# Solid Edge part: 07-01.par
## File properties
Author: edge
Template: jis part.par
Last saved by: edge
Revision: 25
Application: Solid Edge
Material: 鋼鉄
面のスタイル: Steel
塗りつぶしのスタイル: ANSI32(Steel)
バーチャルスタイル: 鋼鉄 機械仕上げ
Coef. of Thermal Exp: 0.0
Thermal Conductivity: 32.0
Specific Heat: 481.0
Modulus of Elasticity: 199947953000.0
Poisson's Ratio: 0.29
Yield Stress: 262000766.0
Ultimate Stress: 358527364.0
Elongation: 0.0
文書内容のタイプ: 0
Density: 7833.000 kg/m^3
Accuracy: 0.990
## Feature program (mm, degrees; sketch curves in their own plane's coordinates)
sketch for "ExtrudedProtrusion_1" plane through (0, 0, 0) normal (1, 0, 0) x-axis (0, 1, 0)
  circle centre (0, 0) radius 20
extrude "ExtrudedProtrusion_1" add finite 150 along +normal  FiniteDepth2 = 150 mm
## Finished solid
Body 1: solid body, 3 faces, 2 edges, 0 vertices.
  Faces by surface: plane 2, cylinder 1
  Edges by curve: circle 2
Bounding box of the edges (mm): 300.000 x 40.000 x 40.000, from (-150, -20, -20) to (150, 20, 20).
Cylindrical faces by radius (mm): R20 x1
Planar faces by outward normal: +x 1, -x 1
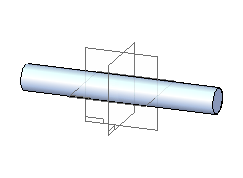
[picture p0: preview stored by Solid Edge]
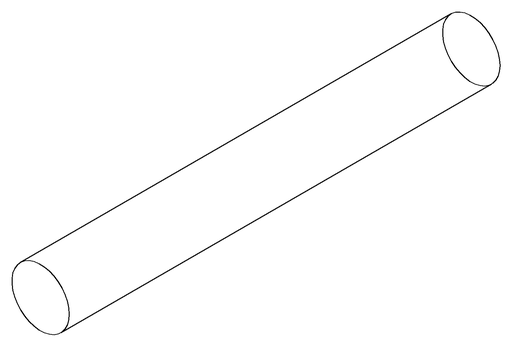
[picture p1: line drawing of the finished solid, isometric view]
